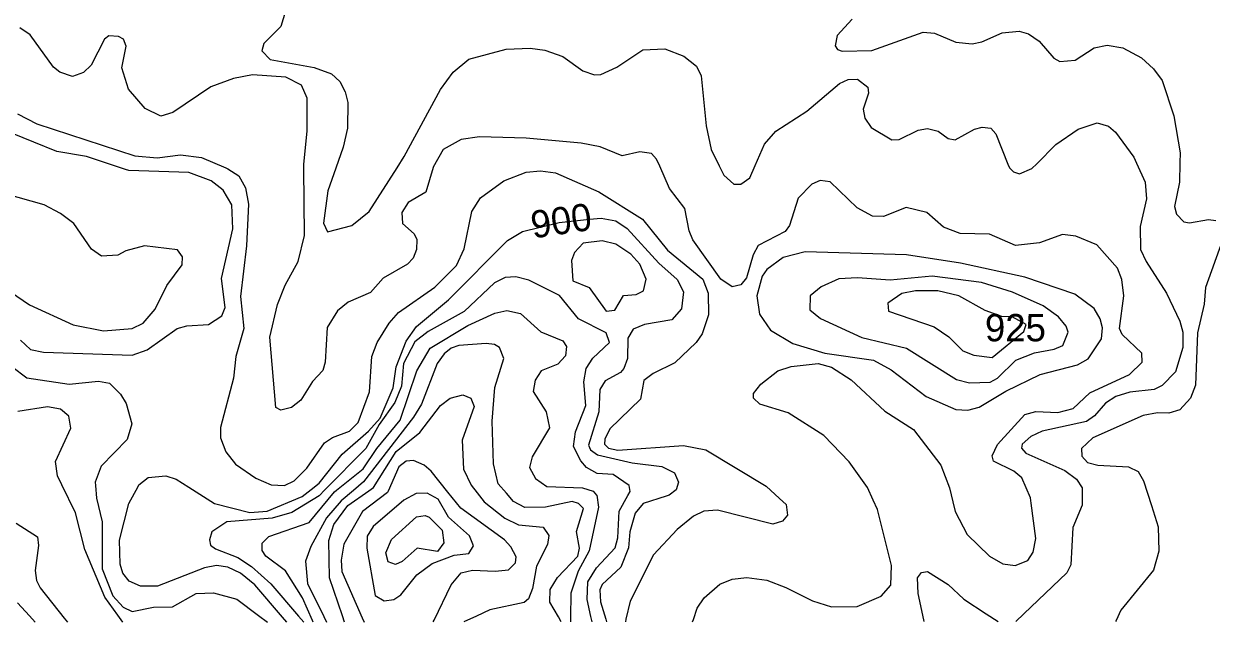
# Model space of a CAD drawing. Extents: x 473.9 to 500, y 7733.1 to 7760.8.
# Drawn here: x 485.784 to 489.264, y 7733.148 to 7734.902 of the extents above; entities that cross this region are included whole.
import ezdxf
from ezdxf.enums import TextEntityAlignment as Align

# ---------------------------------------------------------------- set-up
doc = ezdxf.new("R2010")
doc.units = 0
doc.header["$LTSCALE"] = 0.032
doc.layers.add('1', color=7, linetype='Continuous', lineweight=25)
doc.layers.add('2', color=7, linetype='Continuous', lineweight=13)
doc.layers.add('21', color=7, linetype='Continuous')
doc.layers.add('61', color=7, linetype='Continuous')

msp = doc.modelspace()

# ---------------------------------------------------------------- linework, layer by layer
at = {"layer": '1'}
for points in [[(485.7743, 7733.9747), (485.8036, 7733.9468), (485.8416, 7733.9388), (486.1019, 7733.9305), (486.1459, 7733.9463), (486.2333, 7734.0083), (486.2624, 7734.0168), (486.3255, 7734.0207), (486.3643, 7734.0455), (486.3747, 7734.0702), (486.3636, 7734.1551), (486.3964, 7734.3003), (486.3941, 7734.3714), (486.3688, 7734.4139), (486.3329, 7734.4417), (486.2674, 7734.466), (486.0921, 7734.4712), (486.0827, 7734.4743), (485.9679, 7734.5124), (485.8806, 7734.5272), (485.7466, 7734.5822)], [(486.5552, 7733.1481), (486.5425, 7733.1628), (486.4611, 7733.2571), (486.4196, 7733.2915), (486.3823, 7733.3093), (486.3484, 7733.3135), (486.3136, 7733.3072), (486.1764, 7733.2538), (486.1262, 7733.2533), (486.0934, 7733.2679), (486.0741, 7733.2914), (486.0664, 7733.3181), (486.0651, 7733.3879), (486.0922, 7733.4958), (486.1193, 7733.5459), (486.1215, 7733.55), (486.1485, 7733.5721), (486.2001, 7733.5764), (486.2306, 7733.5666), (486.268, 7733.5431), (486.343, 7733.4959), (486.4462, 7733.4697), (486.497, 7733.4729), (486.6003, 7733.5162), (486.626, 7733.5363), (486.6497, 7733.5548), (486.7169, 7733.6398), (486.7945, 7733.7077), (486.8282, 7733.7453), (486.8666, 7733.8348), (486.8751, 7733.8963), (486.9044, 7733.9717), (486.9345, 7734.0146), (487.0285, 7734.0928), (487.2016, 7734.266), (487.2453, 7734.2931), (487.353, 7734.3191), (487.4418, 7734.3292), (487.4761, 7734.3321), (487.5191, 7734.3236), (487.5526, 7734.3018), (487.6447, 7734.2001), (487.699, 7734.152), (487.7175, 7734.1162), (487.7117, 7734.0663), (487.6834, 7734.0342), (487.6033, 7734.0204), (487.5694, 7734.0063), (487.5537, 7733.9802), (487.5536, 7733.9204), (487.5427, 7733.8913), (487.5323, 7733.8797), (487.4876, 7733.8547), (487.4722, 7733.8301), (487.469, 7733.764), (487.4393, 7733.6667), (487.4448, 7733.6525), (487.4651, 7733.6386), (487.5664, 7733.6144), (487.6537, 7733.6037), (487.6908, 7733.5853), (487.7022, 7733.5586), (487.6953, 7733.5354), (487.6751, 7733.5196), (487.666, 7733.5167), (487.5987, 7733.4953), (487.5759, 7733.4674), (487.5601, 7733.4123), (487.5561, 7733.3656), (487.534, 7733.3087), (487.4785, 7733.2581), (487.4716, 7733.2426), (487.474, 7733.2077), (487.4892, 7733.1562), (487.4914, 7733.1489)], [(486.9841, 7733.1485), (486.9865, 7733.1535), (487.0364, 7733.2577), (487.0656, 7733.2928), (487.0994, 7733.3007), (487.1656, 7733.297), (487.2048, 7733.3016), (487.2252, 7733.322), (487.2268, 7733.3393), (487.2116, 7733.3691), (487.1932, 7733.3893), (487.0645, 7733.4817), (487.0268, 7733.5288), (486.9774, 7733.5905), (486.9578, 7733.6075), (486.9262, 7733.6215), (486.9042, 7733.6196), (486.8827, 7733.6027), (486.8523, 7733.532), (486.8504, 7733.5276), (486.7768, 7733.472), (486.7217, 7733.376), (486.7141, 7733.3296), (486.7166, 7733.2962), (486.776, 7733.161), (486.7816, 7733.1483)]]:
    msp.add_lwpolyline(points, dxfattribs=at)
msp.add_lwpolyline([(488.5175, 7733.8595), (488.5556, 7733.849), (488.6157, 7733.8517), (488.6373, 7733.8634), (488.6906, 7733.9157), (488.7457, 7733.937), (488.8035, 7733.9475), (488.8289, 7733.9584), (488.8446, 7733.9976), (488.8383, 7734.015), (488.8159, 7734.0426), (488.7713, 7734.0747), (488.6811, 7734.1149), (488.5906, 7734.1434), (488.4457, 7734.1619), (488.3227, 7734.1499), (488.227, 7734.1571), (488.1719, 7734.1536), (488.1207, 7734.1304), (488.0879, 7734.1041), (488.087, 7734.0631), (488.1184, 7734.0378), (488.2402, 7733.9821), (488.3703, 7733.9504)], close=True, dxfattribs=at)
at = {"layer": '2'}
for points in [[(486.5618, 7734.9743), (486.5378, 7734.8937), (486.4874, 7734.8437), (486.4813, 7734.8222), (486.5066, 7734.7971), (486.6352, 7734.7738), (486.6861, 7734.7551), (486.7104, 7734.7326), (486.7263, 7734.7017), (486.7333, 7734.6706), (486.7325, 7734.5961), (486.7199, 7734.5403), (486.6982, 7734.4782), (486.6749, 7734.4117), (486.6624, 7734.3174), (486.6738, 7734.2914), (486.7452, 7734.3101), (486.7966, 7734.3512), (486.8779, 7734.4793), (486.8989, 7734.5125), (487.0056, 7734.7088), (487.0426, 7734.7597), (487.0883, 7734.7976), (487.1981, 7734.8268), (487.2678, 7734.8301), (487.3112, 7734.8243), (487.3632, 7734.8061), (487.4227, 7734.7636), (487.456, 7734.7521), (487.4753, 7734.7533), (487.5218, 7734.7742), (487.5985, 7734.8251), (487.6623, 7734.8284), (487.7181, 7734.8065), (487.7552, 7734.777), (487.7688, 7734.7489), (487.7841, 7734.6021), (487.798, 7734.5329), (487.8217, 7734.4853), (487.8355, 7734.4577), (487.8646, 7734.4318), (487.8855, 7734.4315), (487.912, 7734.4498), (487.9274, 7734.486), (487.9541, 7734.5489), (487.988, 7734.5864), (488.0782, 7734.6455), (488.1744, 7734.7262), (488.2001, 7734.7386), (488.2269, 7734.7397), (488.2575, 7734.7157), (488.2591, 7734.698), (488.2435, 7734.6513), (488.249, 7734.6253), (488.2674, 7734.598), (488.3275, 7734.5615), (488.3489, 7734.562), (488.405, 7734.5902), (488.432, 7734.5944), (488.4631, 7734.5865), (488.4924, 7734.5655), (488.5129, 7734.5616), (488.5703, 7734.5929), (488.5922, 7734.5985), (488.6173, 7734.5961), (488.6321, 7734.5789), (488.6677, 7734.4906), (488.6721, 7734.4797), (488.6838, 7734.4679), (488.7021, 7734.462), (488.7383, 7734.4773), (488.7521, 7734.4912), (488.8086, 7734.5478), (488.8741, 7734.5931), (488.9289, 7734.6111), (488.963, 7734.6015), (488.9829, 7734.584), (489.0365, 7734.511), (489.0448, 7734.493), (489.0704, 7734.4374), (489.0738, 7734.3886), (489.0554, 7734.3077), (489.0567, 7734.2405), (489.0727, 7734.2048), (489.1327, 7734.1116)], [(488.2111, 7734.9154), (488.1677, 7734.8676), (488.1617, 7734.8374), (488.1685, 7734.8257), (488.1821, 7734.8208), (488.2692, 7734.8228), (488.4197, 7734.8766), (488.4528, 7734.874), (488.515, 7734.8478), (488.5632, 7734.8431), (488.5911, 7734.8489), (488.6513, 7734.8749), (488.7009, 7734.88), (488.7277, 7734.872), (488.759, 7734.851), (488.8027, 7734.8004), (488.8195, 7734.7914), (488.8651, 7734.7946), (488.9208, 7734.831), (488.9589, 7734.8389), (489.0049, 7734.8313), (489.059, 7734.802), (489.0944, 7734.7693), (489.1195, 7734.7353), (489.1541, 7734.632), (489.1726, 7734.5231), (489.1718, 7734.4938), (489.1704, 7734.4374), (489.156, 7734.3661), (489.1619, 7734.3431), (489.1832, 7734.3213), (489.1995, 7734.3178), (489.2552, 7734.3283), (489.2767, 7734.3247)], [(487.2565, 7734.5663), (487.1193, 7734.5703), (487.0657, 7734.5621), (487.0132, 7734.5333), (486.984, 7734.4814), (486.9836, 7734.48), (486.9621, 7734.4081), (486.9107, 7734.3778), (486.892, 7734.3485), (486.8943, 7734.3161), (486.9281, 7734.2864), (486.9356, 7734.2695), (486.9353, 7734.2402), (486.9251, 7734.2146), (486.9087, 7734.1972), (486.8375, 7734.1559), (486.8001, 7734.114), (486.7344, 7734.0852), (486.7037, 7734.0605), (486.6736, 7734.0114), (486.6674, 7733.9094), (486.6602, 7733.8854), (486.6305, 7733.8531), (486.5962, 7733.7981), (486.5688, 7733.7765), (486.5371, 7733.7688), (486.5227, 7733.7766), (486.5051, 7733.9834), (486.528, 7734.0789), (486.5504, 7734.1352), (486.5886, 7734.2053), (486.6063, 7734.2809), (486.6049, 7734.4776), (486.6048, 7734.4894), (486.6143, 7734.5875), (486.6144, 7734.6835), (486.5983, 7734.7212), (486.5516, 7734.7448), (486.4546, 7734.752), (486.3984, 7734.7415), (486.3324, 7734.7164), (486.2214, 7734.6418), (486.1853, 7734.6308), (486.1402, 7734.6534), (486.0912, 7734.7096), (486.0717, 7734.772), (486.084, 7734.8364), (486.0767, 7734.8564), (486.0618, 7734.8644), (486.0338, 7734.8662), (486.0208, 7734.8569), (485.982, 7734.7799), (485.9593, 7734.7592), (485.9266, 7734.7466), (485.89, 7734.7601), (485.8717, 7734.7742), (485.803, 7734.8693), (485.7725, 7734.8895)], [(485.7659, 7734.6376), (485.8222, 7734.6086), (486.1096, 7734.5146), (486.1749, 7734.5085), (486.2431, 7734.5172), (486.305, 7734.5095), (486.3765, 7734.4795), (486.3818, 7734.4762), (486.4144, 7734.4558), (486.4336, 7734.4203), (486.443, 7734.3732), (486.4368, 7734.2505), (486.4191, 7734.102), (486.4286, 7734.0085), (486.406, 7733.9266), (486.3989, 7733.8628), (486.3609, 7733.7186), (486.3607, 7733.6881), (486.376, 7733.6467), (486.4046, 7733.6111), (486.4638, 7733.57), (486.5088, 7733.5507), (486.5483, 7733.5481), (486.5762, 7733.5625), (486.6139, 7733.5992), (486.665, 7733.6737), (486.689, 7733.6895), (486.7382, 7733.7077), (486.764, 7733.7332), (486.7968, 7733.8227), (486.804, 7733.9268), (486.8195, 7733.9673), (486.8551, 7734.0241), (486.8825, 7734.0554), (486.9887, 7734.1293), (487.0517, 7734.1931), (487.075, 7734.2424), (487.0973, 7734.3512), (487.1222, 7734.3915), (487.1905, 7734.441), (487.256, 7734.4662), (487.2984, 7734.4705), (487.3424, 7734.4651), (487.4687, 7734.4092), (487.5968, 7734.3291), (487.6701, 7734.2384), (487.7737, 7734.153), (487.7898, 7734.1121), (487.7907, 7734.0483), (487.7716, 7733.9926)], [(487.7438, 7733.149), (487.7462, 7733.156), (487.7575, 7733.1889), (487.7779, 7733.2189), (487.8233, 7733.2592), (487.8601, 7733.2734), (487.9027, 7733.2783), (487.9615, 7733.2706), (488.0175, 7733.2497), (488.0955, 7733.21), (488.1511, 7733.1932), (488.2264, 7733.194), (488.2963, 7733.2241), (488.3244, 7733.2567), (488.3263, 7733.3136), (488.2856, 7733.4779), (488.2731, 7733.5053), (488.2564, 7733.5421), (488.2023, 7733.6177), (488.128, 7733.6952), (488.0242, 7733.7617), (487.9406, 7733.7867), (487.9227, 7733.8041), (487.9226, 7733.8179), (487.9435, 7733.8456), (487.9937, 7733.8847), (488.0326, 7733.8974), (488.1116, 7733.9061), (488.1511, 7733.8953), (488.2084, 7733.8585), (488.307, 7733.7664), (488.3912, 7733.7124), (488.471, 7733.6082), (488.4965, 7733.5413), (488.5065, 7733.5009), (488.5137, 7733.472), (488.5485, 7733.4051), (488.6141, 7733.3412), (488.6528, 7733.3188), (488.6892, 7733.3138), (488.726, 7733.3283), (488.7418, 7733.3532), (488.7498, 7733.3928), (488.7363, 7733.4966), (488.7343, 7733.5122), (488.7087, 7733.5707), (488.685, 7733.5905), (488.6256, 7733.6195), (488.622, 7733.635), (488.6375, 7733.6688), (488.717, 7733.7564), (488.7499, 7733.7655), (488.8137, 7733.7625), (488.8588, 7733.7739), (488.908, 7733.8196), (489.0236, 7733.8737), (489.061, 7733.9096), (489.0601, 7733.9361), (489.0023, 7733.9907), (488.995, 7734.0081), (489.0078, 7734.1046), (489.0015, 7734.1523), (488.9888, 7734.1855), (488.9283, 7734.2535), (488.8672, 7734.2793), (488.8281, 7734.2842), (488.7606, 7734.2592), (488.6898, 7734.2518), (488.6137, 7734.2847), (488.5279, 7734.2866), (488.4788, 7734.3057), (488.4305, 7734.3481), (488.3698, 7734.3635), (488.3028, 7734.3365), (488.2708, 7734.3379), (488.2258, 7734.3618), (488.1465, 7734.4384), (488.118, 7734.4425), (488.093, 7734.4311), (488.0537, 7734.39), (488.0281, 7734.3108), (488.0153, 7734.2927), (487.9362, 7734.2517), (487.9212, 7734.2247), (487.9021, 7734.1567), (487.8854, 7734.1365), (487.8598, 7734.1306), (487.8264, 7734.1535), (487.7447, 7734.2686), (487.7338, 7734.2944), (487.7214, 7734.3598), (487.6761, 7734.4191), (487.6475, 7734.4842), (487.6384, 7734.505), (487.623, 7734.5212), (487.5889, 7734.5261), (487.538, 7734.515), (487.473, 7734.5406), (487.4173, 7734.5517), (487.2565, 7734.5663)], [(485.6485, 7734.1818), (485.8005, 7734.0778), (485.9293, 7734.0197), (486.0173, 7734.0021), (486.1014, 7734.0084), (486.1338, 7734.0244), (486.169, 7734.0656), (486.2037, 7734.1345), (486.248, 7734.1948), (486.249, 7734.2188), (486.2344, 7734.2387), (486.1379, 7734.2503), (486.0837, 7734.2364), (486.06, 7734.2234), (486.0124, 7734.2204), (485.9825, 7734.2408), (485.9309, 7734.3163), (485.892, 7734.3457), (485.8436, 7734.3713), (485.7299, 7734.4031)], [(489.2956, 7734.2645), (489.2471, 7734.1282), (489.2427, 7734.0799), (489.223, 7733.9958), (489.217, 7733.8425), (489.2029, 7733.8043)], [(487.4495, 7733.1488), (487.446, 7733.1643), (487.4348, 7733.2144), (487.4368, 7733.2657), (487.4626, 7733.3069), (487.5168, 7733.3657), (487.5247, 7733.3949), (487.5284, 7733.4732), (487.554, 7733.5188), (487.5606, 7733.5307), (487.5576, 7733.5479), (487.5111, 7733.5806), (487.464, 7733.5837), (487.4334, 7733.6007), (487.4162, 7733.6206), (487.3951, 7733.6626), (487.4008, 7733.7052), (487.4312, 7733.7824), (487.4248, 7733.8521), (487.4324, 7733.8917), (487.4518, 7733.922), (487.5001, 7733.9674), (487.4903, 7733.9962), (487.4096, 7734.0366), (487.3536, 7734.1053), (487.2636, 7734.1502), (487.2259, 7734.1596), (487.1949, 7734.1575), (487.1634, 7734.1428), (487.0746, 7734.0588), (486.9688, 7733.9996), (486.9304, 7733.9691), (486.8966, 7733.9062), (486.8907, 7733.8392), (486.8713, 7733.7916), (486.8256, 7733.7272), (486.786, 7733.6566), (486.6664, 7733.5355), (486.6493, 7733.5183), (486.5693, 7733.4689), (486.512, 7733.4526), (486.379, 7733.4418), (486.3348, 7733.4126), (486.3282, 7733.3895), (486.3316, 7733.3738), (486.3456, 7733.3629), (486.4117, 7733.337), (486.4518, 7733.3109), (486.5083, 7733.2605), (486.5895, 7733.1658), (486.6046, 7733.1482)], [(489.1327, 7734.1116), (489.1718, 7734.0302), (489.1808, 7733.998), (489.1808, 7733.9529), (489.1592, 7733.8811), (489.1201, 7733.8417), (489.0961, 7733.8296), (489.0248, 7733.8218), (488.9841, 7733.8094), (488.9534, 7733.7895), (488.9219, 7733.7528), (488.8979, 7733.7355), (488.7682, 7733.7078), (488.7349, 7733.692), (488.7092, 7733.6692), (488.7077, 7733.6577), (488.72, 7733.6429), (488.8341, 7733.5926), (488.8688, 7733.5669), (488.8855, 7733.5418), (488.8858, 7733.4937), (488.8858, 7733.4903), (488.8582, 7733.4249), (488.8519, 7733.3162), (488.8408, 7733.2921), (488.7145, 7733.1723), (488.6907, 7733.1498)], [(486.6319, 7733.1482), (486.63, 7733.1526), (486.6008, 7733.2196), (486.5506, 7733.2985), (486.4935, 7733.3414), (486.4828, 7733.3575), (486.4824, 7733.3795), (486.5022, 7733.3987), (486.62, 7733.44), (486.6951, 7733.5303), (486.7009, 7733.5349), (486.7788, 7733.5971), (486.8186, 7733.6566), (486.8866, 7733.7402), (486.9357, 7733.8848), (486.9753, 7733.9512), (487.085, 7734.0169), (487.1644, 7734.0534), (487.1991, 7734.0615), (487.2399, 7734.0525), (487.2995, 7733.9987), (487.364, 7733.9728), (487.3749, 7733.9561), (487.371, 7733.9288), (487.3487, 7733.9037), (487.3005, 7733.8847), (487.2825, 7733.8575), (487.2771, 7733.8241), (487.3148, 7733.7642), (487.3243, 7733.7171), (487.2742, 7733.6326), (487.2664, 7733.6007), (487.2839, 7733.5688), (487.3172, 7733.5455), (487.4211, 7733.5413), (487.4527, 7733.5314), (487.4628, 7733.5205), (487.4632, 7733.5201), (487.4682, 7733.4849), (487.4411, 7733.3568), (487.4085, 7733.2978), (487.3871, 7733.2325), (487.3863, 7733.161), (487.3862, 7733.1488)], [(487.7716, 7733.9926), (487.7548, 7733.9678), (487.6917, 7733.9079), (487.6285, 7733.8763), (487.6014, 7733.8557), (487.5913, 7733.801), (487.5013, 7733.7149), (487.4868, 7733.6843), (487.4861, 7733.6692), (487.4974, 7733.658), (487.5251, 7733.6523), (487.7169, 7733.6659), (487.7824, 7733.6525), (487.9594, 7733.5467), (487.9984, 7733.5105), (488.018, 7733.4923), (488.0224, 7733.4617), (488.0072, 7733.444), (487.9786, 7733.4352), (487.8171, 7733.4761), (487.777, 7733.4729), (487.747, 7733.4586), (487.6982, 7733.4199), (487.6295, 7733.3453), (487.5607, 7733.2095), (487.5487, 7733.1562), (487.5471, 7733.1489)], [(487.3592, 7733.1488), (487.3508, 7733.1634), (487.326, 7733.2068), (487.3265, 7733.2432), (487.3481, 7733.2787), (487.4072, 7733.3411), (487.4126, 7733.3643), (487.404, 7733.4134), (487.4239, 7733.4806), (487.4098, 7733.4959), (487.391, 7733.5019), (487.3127, 7733.4848), (487.2527, 7733.4842), (487.2189, 7733.5012), (487.1982, 7733.5255), (487.1745, 7733.5534), (487.1602, 7733.6116), (487.1563, 7733.7369), (487.1646, 7733.8354), (487.1908, 7733.9201), (487.178, 7733.9525), (487.1638, 7733.9617), (487.1391, 7733.965), (487.0585, 7733.9583), (487.0369, 7733.9509), (487.0156, 7733.9344), (486.9959, 7733.9056), (486.9493, 7733.7867), (486.9262, 7733.7488), (486.7797, 7733.5596), (486.7501, 7733.534), (486.7146, 7733.5032), (486.6712, 7733.4539), (486.6251, 7733.3692), (486.6101, 7733.3262), (486.6158, 7733.2613), (486.6635, 7733.1642), (486.6713, 7733.1482)], [(485.7493, 7733.8967), (485.793, 7733.864), (485.9171, 7733.8452), (486.0028, 7733.854), (486.0352, 7733.8481), (486.0676, 7733.8156), (486.084, 7733.7883), (486.1007, 7733.7294), (486.0867, 7733.6829), (486.011, 7733.6051), (485.9935, 7733.5578), (485.9942, 7733.5482), (485.9968, 7733.5113), (486.0137, 7733.4415), (486.0137, 7733.3038), (486.0451, 7733.2251), (486.0757, 7733.1922), (486.1017, 7733.1787), (486.1641, 7733.1922), (486.2203, 7733.1924), (486.2895, 7733.2317), (486.3405, 7733.2342), (486.4085, 7733.2148), (486.4721, 7733.1674), (486.498, 7733.1481)], [(486.7242, 7733.1483), (486.7179, 7733.1666), (486.6795, 7733.2781), (486.6779, 7733.3868), (486.6926, 7733.4341), (486.7341, 7733.4897), (486.7954, 7733.5331), (486.8085, 7733.5424), (486.8752, 7733.6477), (486.9444, 7733.7033), (487.0052, 7733.7826), (487.0333, 7733.804), (487.071, 7733.8145), (487.0944, 7733.8039), (487.1039, 7733.7798), (487.0687, 7733.6811), (487.0731, 7733.596), (487.0949, 7733.5497), (487.1126, 7733.5271), (487.1336, 7733.5003), (487.1934, 7733.453), (487.234, 7733.4334), (487.3063, 7733.4261), (487.3227, 7733.4018), (487.3187, 7733.3751), (487.2862, 7733.3119), (487.2748, 7733.247), (487.2631, 7733.2158), (487.2502, 7733.2054), (487.1499, 7733.1842), (487.1105, 7733.1658), (487.0735, 7733.1485)], [(489.2029, 7733.8043), (489.1717, 7733.7701), (489.139, 7733.76), (489.1063, 7733.7615), (489.0645, 7733.7535), (488.9165, 7733.688), (488.8834, 7733.6564), (488.8844, 7733.6348), (488.9007, 7733.6161), (488.931, 7733.6081), (489.021, 7733.6031), (489.0497, 7733.5899), (489.0651, 7733.5616), (489.0881, 7733.4899), (489.1083, 7733.4271), (489.11, 7733.3564), (489.0947, 7733.3001), (488.9986, 7733.1831), (488.9847, 7733.153), (488.9833, 7733.15)], [(486.0742, 7733.1478), (486.0594, 7733.1682), (486.0213, 7733.2207), (485.9632, 7733.3611), (485.9361, 7733.4678), (485.8959, 7733.5501), (485.8827, 7733.5771), (485.8771, 7733.6192), (485.9217, 7733.7165), (485.9158, 7733.7514), (485.8919, 7733.7717), (485.8537, 7733.7792), (485.7664, 7733.7648)], [(485.7623, 7733.4377), (485.8242, 7733.3976), (485.8272, 7733.3724), (485.8176, 7733.2995), (485.8213, 7733.2697), (485.8322, 7733.2481), (485.9029, 7733.1594), (485.9123, 7733.1476)], [(488.4221, 7733.1496), (488.4181, 7733.1688), (488.4048, 7733.2321), (488.4032, 7733.2779), (488.4147, 7733.2934), (488.4321, 7733.2961), (488.4925, 7733.2582), (488.5385, 7733.2152), (488.6044, 7733.1723), (488.6391, 7733.1497)], [(485.8176, 7733.1476), (485.8006, 7733.1663), (485.7661, 7733.2042)]]:
    msp.add_lwpolyline(points, dxfattribs=at)
for points in [[(487.5998, 7734.1192), (487.6083, 7734.1531), (487.5891, 7734.1967), (487.5634, 7734.2265), (487.5187, 7734.2556), (487.4785, 7734.2655), (487.4234, 7734.2589), (487.3977, 7734.2316), (487.3887, 7734.2078), (487.3926, 7734.1479), (487.4409, 7734.1289), (487.4911, 7734.0595), (487.5159, 7734.0625), (487.541, 7734.1053), (487.5787, 7734.108)], [(488.6615, 7733.8245), (488.7622, 7733.8737), (488.8715, 7733.902), (488.9025, 7733.9193), (488.9417, 7733.978), (488.9452, 7734.0103), (488.9383, 7734.0365), (488.9202, 7734.067), (488.864, 7734.1096), (488.7172, 7734.1589), (488.5285, 7734.1995), (488.3709, 7734.2246), (488.0734, 7734.2336), (488.009, 7734.2169), (487.9616, 7734.1816), (487.948, 7734.1614), (487.9322, 7734.104), (487.9395, 7734.0506), (487.9723, 7734.0038), (488.038, 7733.9646), (488.1318, 7733.9364), (488.2737, 7733.916), (488.3254, 7733.8872), (488.4281, 7733.8094), (488.5153, 7733.7707), (488.5499, 7733.7691), (488.5832, 7733.7781)], [(488.5683, 7733.9305), (488.622, 7733.9233), (488.7146, 7734.0001), (488.7217, 7734.0203), (488.6807, 7734.0429), (488.6503, 7734.0432), (488.6012, 7734.0609), (488.5242, 7734.1041), (488.462, 7734.1193), (488.3971, 7734.1193), (488.3569, 7734.1111), (488.316, 7734.0825), (488.3178, 7734.0589), (488.4521, 7734.0135), (488.4945, 7733.9838), (488.5361, 7733.9434)], [(486.9356, 7733.2867), (486.981, 7733.3201), (487.0453, 7733.3442), (487.0885, 7733.3493), (487.1024, 7733.3713), (487.0899, 7733.4004), (487.0285, 7733.4553), (486.9987, 7733.5087), (486.9665, 7733.5259), (486.9335, 7733.5252), (486.8979, 7733.5054), (486.8077, 7733.4282), (486.7908, 7733.4002), (486.789, 7733.3648), (486.8136, 7733.2262), (486.84, 7733.2103), (486.8683, 7733.2144), (486.8888, 7733.2279)], [(486.8446, 7733.3506), (486.8621, 7733.3901), (486.9348, 7733.4561), (486.9604, 7733.4601), (486.9724, 7733.4554), (487.0098, 7733.4174), (487.0153, 7733.3799), (486.9961, 7733.3551), (486.9366, 7733.3649), (486.893, 7733.3253), (486.8733, 7733.3169), (486.8514, 7733.3248)]]:
    msp.add_lwpolyline(points, close=True, dxfattribs=at)

# ---------------------------------------------------------------- texts
at = {"layer": '21'}
msp.add_text('925', height=0.08, dxfattribs=at).set_placement((488.6006, 7733.9709))
at = {"layer": '61'}
msp.add_text('900', height=0.08, rotation=8.344, dxfattribs=at).set_placement((487.3644, 7734.2851), align=Align.CENTER)

doc.saveas('drawing.dxf')
